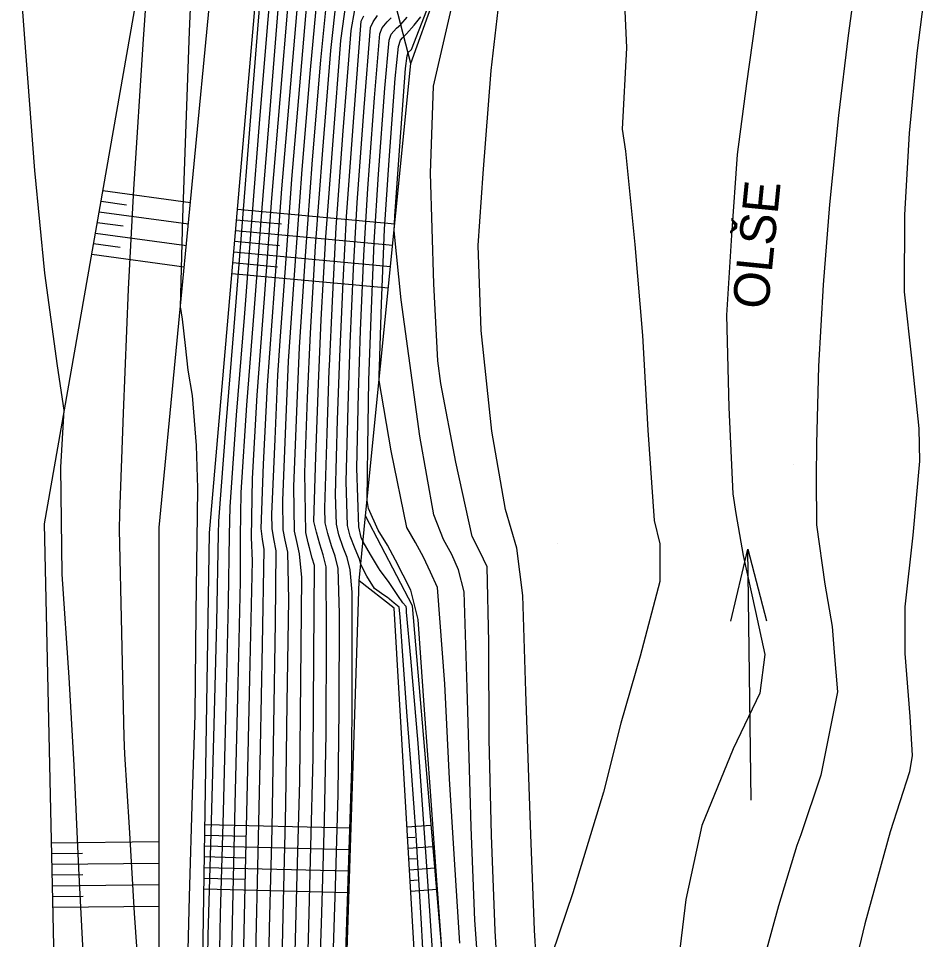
# Model space of a CAD drawing. Extents: x -448957 to -448612, y -1107690 to -1107245.
# Drawn here: x -448732.47 to -448707.02, y -1107599.23 to -1107573.54 of the extents above; entities that cross this region are included whole.
import ezdxf

# ---------------------------------------------------------------- set-up
doc = ezdxf.new("R2010")
doc.units = 0
for name, color, linetype in [('Default', 7, 'Continuous'), ('Vrstva 1', 7, 'Continuous'), ('Vrstva 10', 7, 'Continuous'), ('Vrstva 14', 7, 'Continuous'), ('Vrstva 15', 7, 'Continuous'), ('Vrstva 16', 7, 'Continuous'), ('Vrstva 17', 7, 'Continuous'), ('Vrstva 45', 7, 'Continuous')]:
    doc.layers.add(name, color=color, linetype=linetype)

# ---------------------------------------------------------------- blocks, each defined once
blk = doc.blocks.new('POINT_DISPLAY')
at = {"layer": 'Default'}
blk.add_line((0, 0), (0, 0), dxfattribs=at)
blk = doc.blocks.new('TOK')
at = {"layer": 'Default'}
for p, q in [((-5, 50), (0, 70)), ((0, 0), (0, 70)), ((0, 70), (5, 50))]:
    blk.add_line(p, q, dxfattribs=at)

msp = doc.modelspace()

# ---------------------------------------------------------------- linework, layer by layer
at = {"layer": 'Vrstva 10'}
for p, q in [((-448728.543, -1107587.737), (-448726.935, -1107571.041)), ((-448727.137, -1107587.888), (-448725.702, -1107571.241)), ((-448728.548, -1107604.892), (-448728.543, -1107587.737)), ((-448727.409, -1107605.1), (-448727.137, -1107587.888))]:
    msp.add_line(p, q, dxfattribs=at)
at = {"layer": 'Vrstva 14'}
for p, q in [((-448721.518, -1107574.799), (-448713.362, -1107551.982)), ((-448731.748, -1107587.639), (-448728.815, -1107570.953)), ((-448721.518, -1107574.799), (-448721.944, -1107573.142)), ((-448722.781, -1107587.417), (-448721.518, -1107574.799)), ((-448722.967, -1107589.231), (-448722.781, -1107587.417)), ((-448721.474, -1107589.923), (-448722.781, -1107587.417)), ((-448731.353, -1107604.923), (-448731.748, -1107587.639)), ((-448723.466, -1107604.692), (-448722.967, -1107589.231)), ((-448721.986, -1107589.993), (-448722.967, -1107589.231)), ((-448721.115, -1107604.828), (-448721.986, -1107589.993)), ((-448720.198, -1107604.84), (-448721.474, -1107589.923))]:
    msp.add_line(p, q, dxfattribs=at)
at = {"layer": 'Vrstva 15'}
for p, q in [((-448730.114, -1107578.343), (-448727.67, -1107578.675)), ((-448730.166, -1107578.639), (-448729.454, -1107578.735)), ((-448730.218, -1107578.934), (-448727.728, -1107579.272)), ((-448726.359, -1107578.857), (-448721.965, -1107579.267)), ((-448730.27, -1107579.23), (-448729.545, -1107579.328)), ((-448726.384, -1107579.156), (-448725.131, -1107579.273)), ((-448730.322, -1107579.526), (-448727.785, -1107579.87)), ((-448726.41, -1107579.455), (-448722.025, -1107579.864)), ((-448730.374, -1107579.821), (-448729.636, -1107579.922)), ((-448726.436, -1107579.754), (-448725.185, -1107579.871)), ((-448730.426, -1107580.117), (-448727.843, -1107580.468)), ((-448726.462, -1107580.053), (-448722.085, -1107580.461)), ((-448726.487, -1107580.352), (-448725.239, -1107580.468)), ((-448726.513, -1107580.651), (-448722.144, -1107581.058)), ((-448727.266, -1107596.021), (-448723.189, -1107596.119)), ((-448721.628, -1107596.088), (-448720.951, -1107596.039)), ((-448731.545, -1107596.533), (-448728.546, -1107596.499)), ((-448727.27, -1107596.321), (-448726.108, -1107596.349)), ((-448721.611, -1107596.387), (-448721.413, -1107596.373)), ((-448727.275, -1107596.621), (-448723.209, -1107596.719)), ((-448721.593, -1107596.687), (-448720.9, -1107596.637)), ((-448731.538, -1107596.833), (-448730.685, -1107596.823)), ((-448727.28, -1107596.921), (-448726.121, -1107596.949)), ((-448721.575, -1107596.986), (-448721.373, -1107596.971)), ((-448731.531, -1107597.133), (-448728.546, -1107597.099)), ((-448727.284, -1107597.221), (-448723.228, -1107597.319)), ((-448721.558, -1107597.286), (-448720.849, -1107597.234)), ((-448731.524, -1107597.432), (-448730.675, -1107597.423)), ((-448727.289, -1107597.521), (-448726.133, -1107597.549)), ((-448721.54, -1107597.585), (-448721.333, -1107597.57)), ((-448731.517, -1107597.732), (-448728.546, -1107597.699)), ((-448727.294, -1107597.821), (-448723.247, -1107597.918)), ((-448721.523, -1107597.885), (-448720.797, -1107597.832)), ((-448731.51, -1107598.032), (-448730.665, -1107598.023)), ((-448731.504, -1107598.332), (-448728.546, -1107598.299))]:
    msp.add_line(p, q, dxfattribs=at)
at = {"layer": 'Vrstva 16'}
for points in [[(-448715.724, -1107569.397), (-448715.504, -1107574.358), (-448715.62, -1107576.632), (-448715.529, -1107577.238), (-448715.271, -1107579.844), (-448715.059, -1107582.382), (-448714.908, -1107585.023), (-448714.733, -1107587.546), (-448714.569, -1107588.197), (-448714.569, -1107589.244), (-448715.119, -1107591.333), (-448715.66, -1107593.2), (-448716.143, -1107595.118), (-448716.998, -1107597.929), (-448717.572, -1107599.627)], [(-448729.093, -1107600.485), (-448729.234, -1107598.494), (-448729.368, -1107596.11), (-448729.5, -1107594.062), (-448729.525, -1107593.588), (-448729.586, -1107590.681), (-448729.648, -1107587.8), (-448729.638, -1107587.345), (-448729.541, -1107584.552), (-448729.402, -1107581.093), (-448729.254, -1107578.302), (-448728.984, -1107574.121), (-448728.781, -1107571.332)], [(-448718.027, -1107599.738), (-448718.073, -1107598.975), (-448718.175, -1107596.307), (-448718.31, -1107592.311), (-448718.395, -1107589.635), (-448718.559, -1107588.312), (-448718.883, -1107587.239), (-448719.261, -1107585.051), (-448719.561, -1107582.249), (-448719.643, -1107579.873), (-448719.505, -1107577.863), (-448719.282, -1107574.988), (-448718.996, -1107572.567)], [(-448724.462, -1107601.792), (-448724.38, -1107599.219), (-448724.307, -1107596.644), (-448724.249, -1107594.155), (-448724.227, -1107591.321), (-448724.213, -1107588.8), (-448724.27, -1107588.594), (-448724.352, -1107588.304), (-448724.387, -1107588.168), (-448724.455, -1107587.877), (-448724.477, -1107586.21), (-448724.403, -1107584.122), (-448724.323, -1107582.323), (-448724.178, -1107579.896), (-448723.979, -1107577.216), (-448723.754, -1107574.43), (-448723.581, -1107572.911)], [(-448726.198, -1107600.266), (-448726.136, -1107597.339), (-448726.069, -1107594.478), (-448726.003, -1107591.534), (-448725.941, -1107588.671), (-448725.966, -1107588.021), (-448725.943, -1107586.369), (-448725.809, -1107584.05), (-448725.604, -1107581.355), (-448725.395, -1107578.555), (-448725.166, -1107575.805), (-448724.934, -1107573.024)], [(-448720.919, -1107599.537), (-448721.084, -1107597.052), (-448721.317, -1107593.759), (-448721.521, -1107591.386), (-448721.637, -1107590.104), (-448721.646, -1107590.004), (-448721.654, -1107589.944), (-448721.664, -1107589.934), (-448721.746, -1107589.844), (-448721.887, -1107589.635), (-448722.147, -1107589.246), (-448722.376, -1107588.94), (-448722.426, -1107588.869), (-448722.648, -1107588.489), (-448722.855, -1107588.136), (-448722.878, -1107588.082), (-448722.905, -1107588.014), (-448722.973, -1107587.723), (-448723.023, -1107586.082), (-448722.982, -1107583.997), (-448722.921, -1107582.242), (-448722.834, -1107580.152), (-448722.722, -1107578.28), (-448722.533, -1107575.755), (-448722.384, -1107573.968), (-448722.321, -1107573.806), (-448722.182, -1107573.636), (-448722.065, -1107573.519)]]:
    msp.add_lwpolyline(points, dxfattribs=at)
at = {"layer": 'Vrstva 17'}
for points in [[(-448719.079, -1107600.4), (-448719.17, -1107598.989), (-448719.269, -1107596.319), (-448719.332, -1107593.646), (-448719.341, -1107590.938), (-448719.394, -1107588.836), (-448719.591, -1107588.41), (-448719.808, -1107587.992), (-448720.264, -1107585.92), (-448720.681, -1107583.726), (-448720.766, -1107583.092), (-448720.879, -1107580.942), (-448720.968, -1107577.859), (-448720.885, -1107575.427), (-448719.815, -1107570.793)], [(-448727.732, -1107599.522), (-448727.693, -1107598.041), (-448727.61, -1107595.179), (-448727.536, -1107592.974), (-448727.507, -1107590.116), (-448727.477, -1107587.392), (-448727.464, -1107586.646), (-448727.498, -1107585.456), (-448727.614, -1107584.057), (-448727.73, -1107583.348), (-448727.808, -1107582.667), (-448727.892, -1107581.929), (-448727.936, -1107581.631), (-448727.952, -1107581.598), (-448727.886, -1107579.094), (-448727.701, -1107573.907), (-448727.577, -1107571.118)], [(-448708.889, -1107570.882), (-448709.316, -1107574.016), (-448709.589, -1107576.249), (-448709.836, -1107578.726), (-448710.013, -1107580.973), (-448710.144, -1107583.244), (-448710.204, -1107585.405), (-448710.207, -1107586.355), (-448710.202, -1107587.669), (-448709.971, -1107589.321), (-448709.758, -1107590.501), (-448709.702, -1107591.222), (-448709.617, -1107592.322), (-448710.077, -1107594.649), (-448710.64, -1107596.31), (-448710.744, -1107596.605), (-448711.26, -1107598.295), (-448711.874, -1107600.534)], [(-448725.865, -1107625.073), (-448726.149, -1107623.353), (-448726.433, -1107621.659), (-448726.606, -1107620.411), (-448726.682, -1107618.496), (-448726.798, -1107615.986), (-448726.944, -1107613.106), (-448727.069, -1107610.597), (-448727.182, -1107607.833), (-448727.278, -1107605.324), (-448727.275, -1107604.846), (-448727.227, -1107602.006), (-448727.177, -1107599.121), (-448727.094, -1107596.265), (-448727.007, -1107593.248), (-448726.937, -1107590.387), (-448726.884, -1107587.917), (-448726.88, -1107587.56), (-448726.67, -1107584.878), (-448726.447, -1107582.141), (-448726.229, -1107579.348), (-448726.012, -1107576.627), (-448725.79, -1107573.838), (-448725.585, -1107571.319)], [(-448726.884, -1107601.426), (-448726.83, -1107598.527), (-448726.752, -1107595.669), (-448726.672, -1107592.677), (-448726.605, -1107589.815), (-448726.578, -1107587.951), (-448726.567, -1107587.163), (-448726.383, -1107584.602), (-448726.166, -1107581.879), (-448725.951, -1107579.084), (-448725.73, -1107576.353), (-448725.505, -1107573.567), (-448725.324, -1107571.494)], [(-448707.016, -1107571.529), (-448707.395, -1107574.505), (-448707.618, -1107576.745), (-448707.748, -1107579.014), (-448707.753, -1107581.164), (-448707.541, -1107583.101), (-448707.347, -1107584.977), (-448707.326, -1107585.887), (-448707.515, -1107587.952), (-448707.734, -1107589.952), (-448707.732, -1107591.256), (-448707.595, -1107593.016), (-448707.533, -1107594.102), (-448707.6, -1107594.554), (-448708.146, -1107596.226), (-448708.849, -1107598.794), (-448709.267, -1107600.546)], [(-448730.658, -1107599.763), (-448730.784, -1107597.249), (-448730.918, -1107594.367), (-448731.055, -1107591.922), (-448731.254, -1107589.038), (-448731.284, -1107586.06), (-448731.191, -1107584.47), (-448731.384, -1107583.233), (-448731.734, -1107580.641), (-448732.013, -1107577.784), (-448732.257, -1107574.589), (-448732.472, -1107571.738)], [(-448725.509, -1107601.364), (-448725.461, -1107598.911), (-448725.394, -1107596.144), (-448725.343, -1107593.253), (-448725.294, -1107590.385), (-448725.282, -1107588.392), (-448725.344, -1107588.059), (-448725.392, -1107587.766), (-448725.398, -1107587.369), (-448725.311, -1107585.28), (-448725.234, -1107583.487), (-448725.166, -1107582.537), (-448724.973, -1107579.869), (-448724.838, -1107578.026), (-448724.364, -1107572.481)], [(-448725.133, -1107600.653), (-448725.076, -1107598.171), (-448725.008, -1107595.482), (-448724.968, -1107592.632), (-448724.929, -1107589.761), (-448724.953, -1107588.431), (-448725.025, -1107588.096), (-448725.08, -1107587.803), (-448725.091, -1107586.983), (-448725.009, -1107584.894), (-448724.93, -1107583.099), (-448724.748, -1107580.428), (-448724.553, -1107577.757), (-448724.319, -1107574.978), (-448724.099, -1107572.566)], [(-448719.564, -1107601.006), (-448719.738, -1107598.696), (-448719.841, -1107596.101), (-448719.951, -1107592.215), (-448720.033, -1107589.537), (-448720.19, -1107588.923), (-448720.375, -1107588.491), (-448720.607, -1107588.071), (-448720.875, -1107587.382), (-448721.269, -1107585.191), (-448721.793, -1107581.393), (-448721.985, -1107579.465), (-448721.978, -1107579.273), (-448721.97, -1107579.045), (-448721.828, -1107577.1), (-448721.668, -1107574.94), (-448721.624, -1107574.587), (-448721.598, -1107574.487), (-448721.505, -1107574.409), (-448720.799, -1107572.582)], [(-448725.846, -1107599.652), (-448725.781, -1107596.807), (-448725.717, -1107593.874), (-448725.659, -1107591.009), (-448725.611, -1107588.352), (-448725.656, -1107588.067), (-448725.699, -1107587.772), (-448725.631, -1107585.972), (-448725.522, -1107583.774), (-448725.323, -1107581.093), (-448725.116, -1107578.291), (-448724.649, -1107572.752)], [(-448724.756, -1107599.943), (-448724.691, -1107597.43), (-448724.622, -1107594.819), (-448724.593, -1107592.011), (-448724.564, -1107589.137), (-448724.624, -1107588.471), (-448724.706, -1107588.132), (-448724.767, -1107587.84), (-448724.784, -1107586.596), (-448724.706, -1107584.508), (-448724.627, -1107582.711), (-448724.463, -1107580.162), (-448724.266, -1107577.486), (-448724.036, -1107574.704), (-448723.84, -1107572.738)], [(-448724.085, -1107601.062), (-448724.003, -1107598.487), (-448723.927, -1107595.911), (-448723.887, -1107593.489), (-448723.871, -1107590.73), (-448723.879, -1107588.84), (-448723.97, -1107588.498), (-448724.061, -1107588.209), (-448724.154, -1107587.867), (-448724.224, -1107587.575), (-448724.224, -1107587.563), (-448724.168, -1107585.76), (-448724.1, -1107583.736), (-448724.02, -1107581.935), (-448723.892, -1107579.63), (-448723.692, -1107576.945), (-448723.471, -1107574.155), (-448723.322, -1107573.083)], [(-448711.836, -1107573.107), (-448712.156, -1107575.354), (-448712.417, -1107577.333), (-448712.573, -1107579.587), (-448712.709, -1107581.813), (-448712.643, -1107584.394), (-448712.538, -1107586.798), (-448712.455, -1107587.349), (-448712.25, -1107588.524), (-448711.899, -1107590.079), (-448711.642, -1107591.286), (-448711.782, -1107592.357), (-448712.522, -1107593.909), (-448713.399, -1107596.054), (-448713.842, -1107598.12), (-448714.133, -1107600.505)], [(-448725.176, -1107626.54), (-448725.476, -1107624.833), (-448725.753, -1107623.091), (-448726.021, -1107621.41), (-448726.071, -1107620.588), (-448726.093, -1107619.574), (-448726.208, -1107617.064), (-448726.344, -1107614.218), (-448726.45, -1107611.707), (-448726.556, -1107608.968), (-448726.606, -1107606.472), (-448726.587, -1107603.545), (-448726.541, -1107600.846), (-448726.483, -1107597.933), (-448726.411, -1107595.073), (-448726.338, -1107592.105), (-448726.273, -1107589.243), (-448726.272, -1107587.986), (-448726.255, -1107586.766), (-448726.096, -1107584.326), (-448725.885, -1107581.617), (-448725.673, -1107578.82), (-448725.448, -1107576.079), (-448725.219, -1107573.295)], [(-448723.709, -1107600.332), (-448723.626, -1107597.755), (-448723.546, -1107595.179), (-448723.525, -1107592.822), (-448723.514, -1107590.139), (-448723.545, -1107588.879), (-448723.632, -1107588.539), (-448723.733, -1107588.251), (-448723.841, -1107587.903), (-448723.911, -1107587.612), (-448723.924, -1107587.193), (-448723.859, -1107585.105), (-448723.798, -1107583.351), (-448723.793, -1107583.228), (-448723.711, -1107581.425), (-448723.607, -1107579.364), (-448723.405, -1107576.675), (-448723.189, -1107573.881), (-448723.086, -1107573.297)], [(-448723.333, -1107599.603), (-448723.249, -1107597.023), (-448723.165, -1107594.447), (-448723.162, -1107592.156), (-448723.158, -1107589.547), (-448723.211, -1107588.918), (-448723.293, -1107588.579), (-448723.405, -1107588.293), (-448723.529, -1107587.94), (-448723.599, -1107587.649), (-448723.623, -1107586.822), (-448723.567, -1107584.736), (-448723.506, -1107582.981), (-448723.409, -1107580.89), (-448723.319, -1107579.067), (-448723.11, -1107576.299), (-448722.907, -1107573.617), (-448722.829, -1107573.467)], [(-448721.113, -1107600.877), (-448721.225, -1107598.797), (-448721.375, -1107596.32), (-448721.504, -1107594.532), (-448721.631, -1107592.881), (-448721.761, -1107591.051), (-448721.817, -1107590.235), (-448721.85, -1107589.959), (-448721.983, -1107589.848), (-448722.117, -1107589.735), (-448722.137, -1107589.717), (-448722.158, -1107589.702), (-448722.337, -1107589.577), (-448722.533, -1107589.44), (-448722.745, -1107589.093), (-448722.92, -1107588.771), (-448722.936, -1107588.701), (-448722.955, -1107588.62), (-448723.077, -1107588.335), (-448723.217, -1107587.977), (-448723.286, -1107587.686), (-448723.323, -1107586.452), (-448723.274, -1107584.367), (-448723.213, -1107582.611), (-448723.122, -1107580.521), (-448723.021, -1107578.674), (-448722.821, -1107576.027), (-448722.645, -1107573.793), (-448722.575, -1107573.637), (-448722.448, -1107573.46)], [(-448720.667, -1107599.357), (-448720.815, -1107597.325), (-448720.974, -1107595.093), (-448721.139, -1107592.824), (-448721.314, -1107590.309), (-448721.525, -1107589.49), (-448721.735, -1107589.069), (-448721.952, -1107588.651), (-448722.175, -1107588.235), (-448722.431, -1107587.812), (-448722.699, -1107587.208), (-448722.737, -1107586.982), (-448722.72, -1107585.496), (-448722.69, -1107583.628), (-448722.628, -1107581.872), (-448722.546, -1107579.783), (-448722.424, -1107577.887), (-448722.245, -1107575.484), (-448722.123, -1107574.144), (-448722.067, -1107573.976), (-448721.919, -1107573.815), (-448721.799, -1107573.706), (-448721.622, -1107573.503)], [(-448720.156, -1107599.338), (-448720.312, -1107596.851), (-448720.44, -1107594.753), (-448720.568, -1107592.103), (-448720.775, -1107589.413), (-448720.97, -1107588.985), (-448721.163, -1107588.571), (-448721.39, -1107588.158), (-448721.635, -1107587.736), (-448722.07, -1107585.603), (-448722.403, -1107583.639), (-448722.401, -1107583.47), (-448722.397, -1107583.258), (-448722.336, -1107581.502), (-448722.258, -1107579.414), (-448722.126, -1107577.494), (-448721.956, -1107575.212), (-448721.862, -1107574.319), (-448721.813, -1107574.145), (-448721.757, -1107574.085), (-448721.712, -1107574.044), (-448721.646, -1107573.968), (-448721.427, -1107573.725), (-448721.241, -1107573.496)]]:
    msp.add_lwpolyline(points, dxfattribs=at)

# ---------------------------------------------------------------- block references
at = {"layer": 'Vrstva 1', "xscale": 0.1, "yscale": 0.10000000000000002}
for p in [(-448721.518, -1107574.799), (-448721.518, -1107574.799), (-448722.781, -1107587.417), (-448722.781, -1107587.417), (-448731.748, -1107587.639), (-448728.543, -1107587.737), (-448727.137, -1107587.888), (-448722.967, -1107589.231), (-448722.967, -1107589.231), (-448722.967, -1107589.231), (-448721.986, -1107589.993), (-448721.986, -1107589.993), (-448721.474, -1107589.923)]:
    msp.add_blockref('POINT_DISPLAY', p, dxfattribs=at)
at = {"layer": 'Vrstva 14', "xscale": 0.1, "yscale": 0.10000000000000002}
for p in [(-448710.837, -1107585.985), (-448717.433, -1107588.192)]:
    msp.add_blockref('POINT_DISPLAY', p, dxfattribs=at)
at = {"layer": 'Vrstva 45', "xscale": 0.09999999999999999, "yscale": 0.1, "rotation": 0.8064032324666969}
msp.add_blockref('TOK', (-448712.021, -1107595.346), dxfattribs=at)

# ---------------------------------------------------------------- texts
at = {"layer": 'Vrstva 45'}
msp.add_text('OLŠE', height=1, rotation=84.284, dxfattribs=at).set_placement((-448711.553, -1107581.677))

doc.saveas('drawing.dxf')
